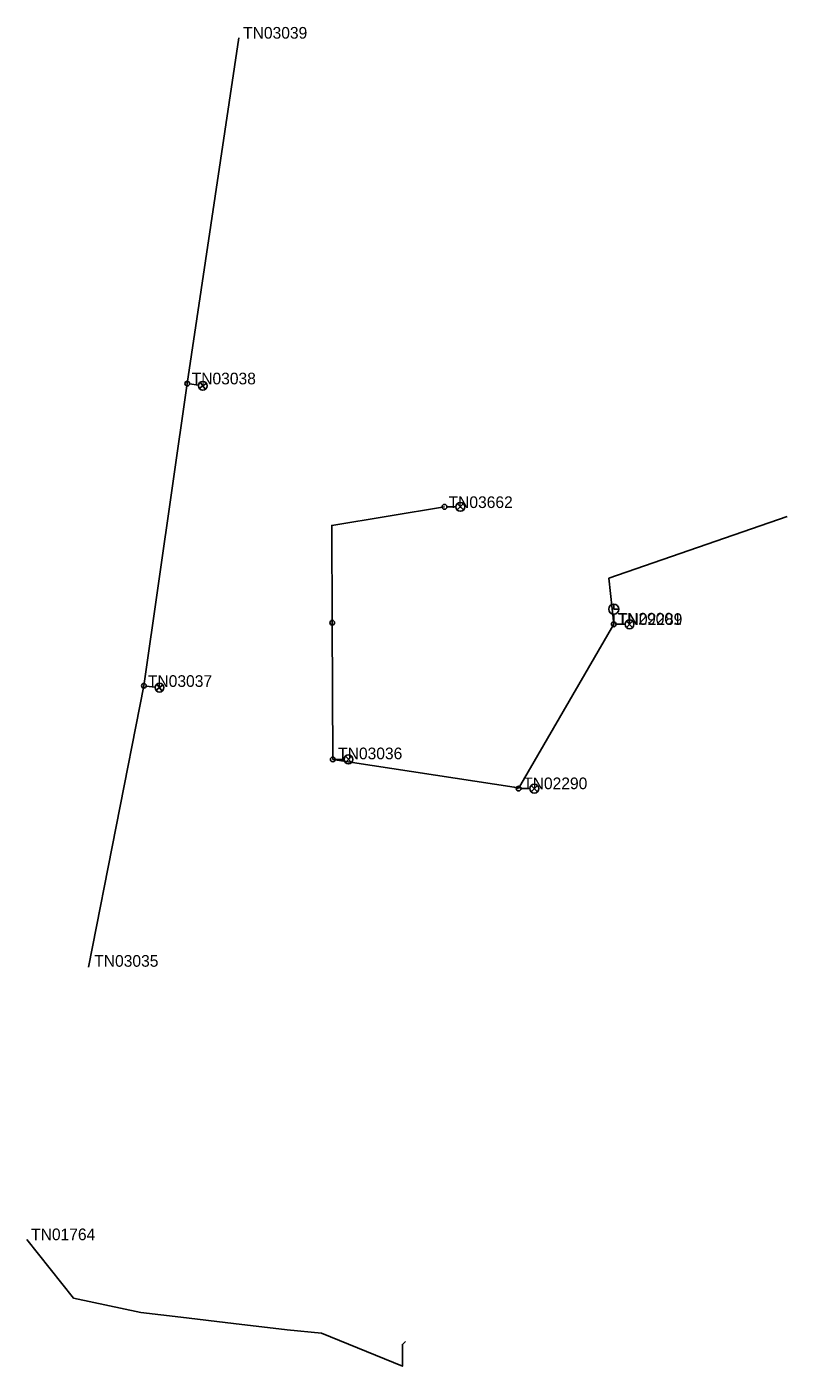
# Model space of a CAD drawing. Extents: x -444529 to -444432, y -1121195 to -1121023.
import ezdxf

# ---------------------------------------------------------------- set-up
doc = ezdxf.new("R2010")
doc.units = 0
for name, color, linetype in [('Hodiny', 7, 'Continuous'), ('Hodiny_popis', 7, 'Continuous'), ('Kabelove_vedeni_zemni', 7, 'Continuous'), ('Pomocny_stozar', 7, 'Continuous'), ('Verejne_osvetleni', 7, 'Continuous'), ('Verejne_osvetleni_popis', 7, 'Continuous')]:
    doc.layers.add(name, color=color, linetype=linetype)

msp = doc.modelspace()

# ---------------------------------------------------------------- linework, layer by layer
at = {"layer": 'Hodiny'}
msp.add_line((-444453.91, -1121098.57), (-444453.91, -1121099.87), dxfattribs=at)
msp.add_lwpolyline([(-444453.91, -1121097.27), (-444453.91, -1121097.27)], close=True, dxfattribs=at)
msp.add_lwpolyline([(-444453.91, -1121097.27), (-444453.91, -1121097.27)], close=True, dxfattribs=at)
msp.add_lwpolyline([(-444453.91, -1121097.27), (-444453.91, -1121097.92), (-444453.26, -1121097.92)], dxfattribs=at)
msp.add_circle((-444453.91, -1121097.92), 0.65, dxfattribs=at)
at = {"layer": 'Kabelove_vedeni_zemni'}
for points in [[(-444508.75, -1121068.91), (-444502.13, -1121024.42)], [(-444514.33, -1121107.77), (-444508.75, -1121068.91)], [(-444490.04, -1121117.25), (-444490.11, -1121099.66), (-444490.18, -1121087.15), (-444475.67, -1121084.76)], [(-444431.6, -1121085.99), (-444454.52, -1121093.94), (-444453.91, -1121099.87)], [(-444466.14, -1121121), (-444453.91, -1121099.87)], [(-444521.44, -1121143.98), (-444514.33, -1121107.77)], [(-444466.14, -1121121), (-444466.7, -1121120.84), (-444490.04, -1121117.25)], [(-444480.68, -1121192.12), (-444481.08, -1121192.5), (-444481.08, -1121195.31), (-444491.48, -1121191.06), (-444495.9, -1121190.63), (-444502.82, -1121189.82), (-444509.56, -1121189.02), (-444514.71, -1121188.41), (-444523.38, -1121186.55), (-444529.38, -1121178.99)]]:
    msp.add_lwpolyline(points, dxfattribs=at)
at = {"layer": 'Pomocny_stozar'}
msp.add_circle((-444490.11, -1121099.66), 0.305, dxfattribs=at)
at = {"layer": 'Verejne_osvetleni'}
for p, q in [((-444508.45, -1121068.95), (-444507.32, -1121069.11)), ((-444506.29, -1121068.84), (-444507.21, -1121069.53)), ((-444506.4, -1121069.65), (-444507.09, -1121068.73)), ((-444475.36, -1121084.76), (-444474.21, -1121084.76)), ((-444473.24, -1121084.35), (-444474.05, -1121085.16)), ((-444473.24, -1121085.16), (-444474.05, -1121084.35)), ((-444453.6, -1121099.87), (-444452.46, -1121099.87)), ((-444451.48, -1121099.46), (-444452.29, -1121100.27)), ((-444451.48, -1121100.27), (-444452.29, -1121099.46)), ((-444514.03, -1121107.81), (-444512.89, -1121107.94)), ((-444511.87, -1121107.66), (-444512.77, -1121108.37)), ((-444511.97, -1121108.46), (-444512.68, -1121107.56)), ((-444489.74, -1121117.25), (-444488.59, -1121117.25)), ((-444487.61, -1121116.84), (-444488.42, -1121117.65)), ((-444487.61, -1121117.65), (-444488.42, -1121116.84)), ((-444463.71, -1121120.59), (-444464.52, -1121121.4)), ((-444463.71, -1121121.4), (-444464.52, -1121120.59)), ((-444465.84, -1121121), (-444464.69, -1121121))]:
    msp.add_line(p, q, dxfattribs=at)
for centre, radius in [((-444508.75, -1121068.91), 0.306), ((-444506.75, -1121069.19), 0.574), ((-444475.67, -1121084.76), 0.306), ((-444473.64, -1121084.76), 0.574), ((-444453.91, -1121099.87), 0.306), ((-444451.88, -1121099.87), 0.574), ((-444514.33, -1121107.77), 0.306), ((-444512.32, -1121108.01), 0.574), ((-444490.04, -1121117.25), 0.306), ((-444488.02, -1121117.25), 0.574), ((-444466.14, -1121121), 0.306), ((-444464.12, -1121121), 0.574)]:
    msp.add_circle(centre, radius, dxfattribs=at)

# ---------------------------------------------------------------- texts
at = {"layer": 'Hodiny_popis'}
msp.add_text('TN29001', height=1.5, dxfattribs=at).set_placement((-444453.42, -1121099.9))
at = {"layer": 'Verejne_osvetleni_popis'}
for s, p in [('TN03039', (-444501.57, -1121024.53)), ('TN03038', (-444508.18, -1121069)), ('TN03662', (-444475.15, -1121084.91)), ('TN02289', (-444453.34, -1121099.96)), ('TN03037', (-444513.81, -1121107.92)), ('TN03036', (-444489.35, -1121117.23)), ('TN02290', (-444465.56, -1121121.08)), ('TN03035', (-444520.71, -1121143.92)), ('TN01764', (-444528.83, -1121179.1))]:
    msp.add_text(s, height=1.5, dxfattribs=at).set_placement(p)

doc.saveas('drawing.dxf')
